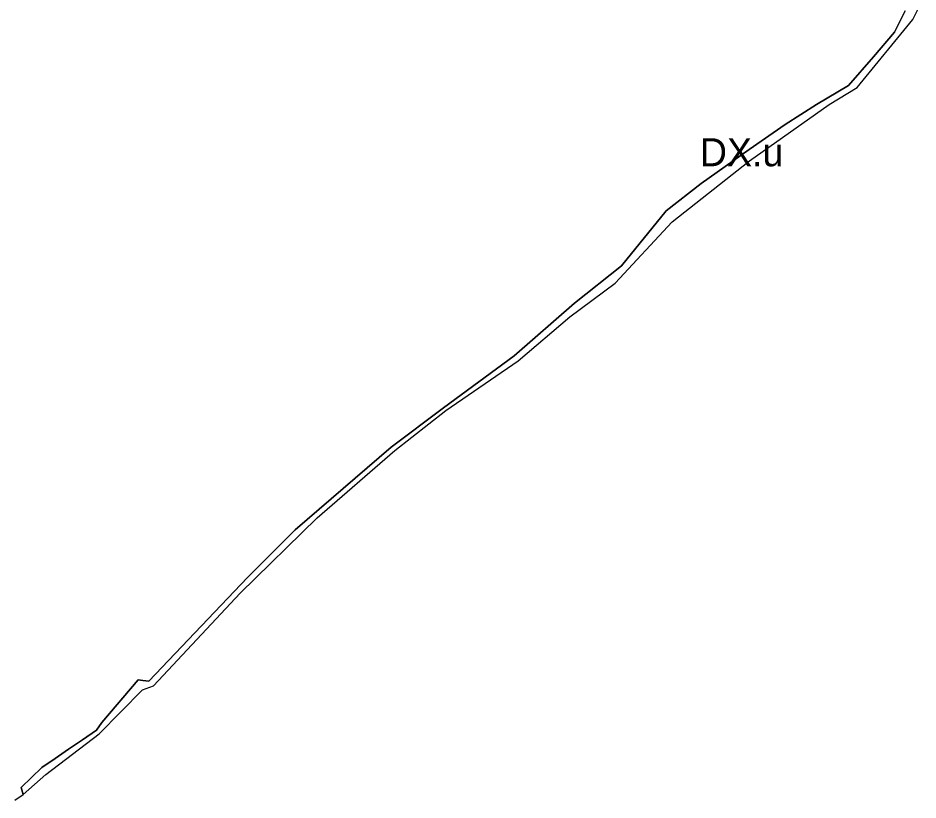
# Model space of a CAD drawing. Extents: x -555509 to -553005, y -1186756 to -1182560.
# Drawn here: x -554001 to -553552.4, y -1186624.2 to -1186234.2 of the extents above; entities that cross this region are included whole.
import ezdxf

# ---------------------------------------------------------------- set-up
doc = ezdxf.new("R2010")
doc.units = 0
for name, color, linetype in [('Level 26', 7, 'Continuous'), ('Level 59', 7, 'Continuous'), ('OBRYS_PLOCH', 7, 'Continuous'), ('stav_AP', 7, 'Continuous')]:
    doc.layers.add(name, color=color, linetype=linetype)

msp = doc.modelspace()

# ---------------------------------------------------------------- linework, layer by layer
at = {"layer": 'Level 26'}
for p, q in [((-553558.79, -1186230.64), (-553564.1, -1186241.28)), ((-553555.07, -1186234.96), (-553552.42, -1186229.64)), ((-553582.79, -1186268.92), (-553555.07, -1186234.96)), ((-553564.1, -1186241.28), (-553574.65, -1186253.6)), ((-553574.65, -1186253.6), (-553587.02, -1186267.86)), ((-553587.02, -1186267.86), (-553603.03, -1186277.36)), ((-553596.76, -1186277.4), (-553582.79, -1186268.92)), ((-553603.03, -1186277.36), (-553618.57, -1186287.3)), ((-553636.33, -1186305.38), (-553596.76, -1186277.4)), ((-553618.57, -1186287.3), (-553636.5, -1186299.75)), ((-553636.5, -1186299.75), (-553660.56, -1186316.81)), ((-553674.91, -1186335.85), (-553636.33, -1186305.38)), ((-553660.56, -1186316.81), (-553678, -1186330.31)), ((-553678, -1186330.31), (-553700.22, -1186357.82)), ((-553703.31, -1186366.52), (-553674.91, -1186335.85)), ((-553700.22, -1186357.82), (-553723.59, -1186376.36)), ((-553725.94, -1186383.17), (-553703.31, -1186366.52)), ((-553723.59, -1186376.36), (-553753.69, -1186402.67)), ((-553751.67, -1186405.15), (-553725.94, -1186383.17)), ((-553753.69, -1186402.67), (-553788.9, -1186428.56)), ((-553787.73, -1186429.86), (-553751.67, -1186405.15)), ((-553788.9, -1186428.56), (-553815, -1186448.15)), ((-553813.2, -1186449.85), (-553787.73, -1186429.86)), ((-553815, -1186448.15), (-553862.84, -1186489.41)), ((-553851.86, -1186483.47), (-553813.2, -1186449.85)), ((-553890.24, -1186521.07), (-553851.86, -1186483.47)), ((-553862.84, -1186489.41), (-553886.65, -1186513.24)), ((-553886.65, -1186513.24), (-553935.74, -1186564.89)), ((-553933.5, -1186567.28), (-553890.24, -1186521.07)), ((-553941.21, -1186564.15), (-553959.17, -1186585.56)), ((-553938.83, -1186564.61), (-553941.21, -1186564.15)), ((-553938.94, -1186569.22), (-553933.5, -1186567.28)), ((-553935.74, -1186564.89), (-553938.83, -1186564.61)), ((-553960.55, -1186591.17), (-553938.94, -1186569.22)), ((-553959.17, -1186585.56), (-553961.95, -1186589.32)), ((-553987.15, -1186611.42), (-553960.55, -1186591.17)), ((-553961.95, -1186589.32), (-553968.89, -1186594.08)), ((-553968.89, -1186594.08), (-553975.83, -1186598.76)), ((-553975.83, -1186598.76), (-553982.5, -1186603.44)), ((-553982.5, -1186603.44), (-553989.2, -1186607.89)), ((-553989.2, -1186607.89), (-553999.39, -1186617.91)), ((-553998.51, -1186621.48), (-553987.15, -1186611.42)), ((-553999.39, -1186617.91), (-553998.51, -1186621.48))]:
    msp.add_line(p, q, dxfattribs=at)
at = {"layer": 'OBRYS_PLOCH'}
for p, q in [((-553558.79, -1186230.64), (-553564.1, -1186241.28)), ((-553564.1, -1186241.28), (-553558.79, -1186230.64)), ((-553555.07, -1186234.96), (-553552.42, -1186229.64)), ((-553582.79, -1186268.92), (-553555.07, -1186234.96)), ((-553564.1, -1186241.28), (-553574.65, -1186253.6)), ((-553574.65, -1186253.6), (-553564.1, -1186241.28)), ((-553574.65, -1186253.6), (-553587.02, -1186267.86)), ((-553587.02, -1186267.86), (-553574.65, -1186253.6)), ((-553587.02, -1186267.86), (-553603.03, -1186277.36)), ((-553603.03, -1186277.36), (-553587.02, -1186267.86)), ((-553596.76, -1186277.4), (-553582.79, -1186268.92)), ((-553603.03, -1186277.36), (-553618.57, -1186287.3)), ((-553618.57, -1186287.3), (-553603.03, -1186277.36)), ((-553636.33, -1186305.38), (-553596.76, -1186277.4)), ((-553618.57, -1186287.3), (-553636.5, -1186299.75)), ((-553636.5, -1186299.75), (-553618.57, -1186287.3)), ((-553636.5, -1186299.75), (-553660.56, -1186316.81)), ((-553660.56, -1186316.81), (-553636.5, -1186299.75)), ((-553674.91, -1186335.85), (-553636.33, -1186305.38)), ((-553660.56, -1186316.81), (-553678, -1186330.31)), ((-553678, -1186330.31), (-553660.56, -1186316.81)), ((-553678, -1186330.31), (-553700.22, -1186357.82)), ((-553700.22, -1186357.82), (-553678, -1186330.31)), ((-553703.31, -1186366.52), (-553674.91, -1186335.85)), ((-553700.22, -1186357.82), (-553723.59, -1186376.36)), ((-553723.59, -1186376.36), (-553700.22, -1186357.82)), ((-553725.94, -1186383.17), (-553703.31, -1186366.52)), ((-553723.59, -1186376.36), (-553753.69, -1186402.67)), ((-553753.69, -1186402.67), (-553723.59, -1186376.36)), ((-553751.67, -1186405.15), (-553725.94, -1186383.17)), ((-553753.69, -1186402.67), (-553788.9, -1186428.56)), ((-553788.9, -1186428.56), (-553753.69, -1186402.67)), ((-553787.73, -1186429.86), (-553751.67, -1186405.15)), ((-553788.9, -1186428.56), (-553815, -1186448.15)), ((-553815, -1186448.15), (-553788.9, -1186428.56)), ((-553813.2, -1186449.85), (-553787.73, -1186429.86)), ((-553815, -1186448.15), (-553862.84, -1186489.41)), ((-553862.84, -1186489.41), (-553815, -1186448.15)), ((-553851.86, -1186483.47), (-553813.2, -1186449.85)), ((-553890.24, -1186521.07), (-553851.86, -1186483.47)), ((-553862.84, -1186489.41), (-553886.65, -1186513.24)), ((-553886.65, -1186513.24), (-553862.84, -1186489.41)), ((-553886.65, -1186513.24), (-553935.74, -1186564.89)), ((-553935.74, -1186564.89), (-553886.65, -1186513.24)), ((-553933.5, -1186567.28), (-553890.24, -1186521.07)), ((-553941.21, -1186564.15), (-553959.17, -1186585.56)), ((-553959.17, -1186585.56), (-553941.21, -1186564.15)), ((-553938.83, -1186564.61), (-553941.21, -1186564.15)), ((-553941.21, -1186564.15), (-553938.83, -1186564.61)), ((-553938.94, -1186569.22), (-553933.5, -1186567.28)), ((-553935.74, -1186564.89), (-553938.83, -1186564.61)), ((-553938.83, -1186564.61), (-553935.74, -1186564.89)), ((-553960.55, -1186591.17), (-553938.94, -1186569.22)), ((-553959.17, -1186585.56), (-553961.95, -1186589.32)), ((-553961.95, -1186589.32), (-553959.17, -1186585.56)), ((-553987.15, -1186611.42), (-553960.55, -1186591.17)), ((-553961.95, -1186589.32), (-553968.89, -1186594.08)), ((-553968.89, -1186594.08), (-553961.95, -1186589.32)), ((-553968.89, -1186594.08), (-553975.83, -1186598.76)), ((-553975.83, -1186598.76), (-553968.89, -1186594.08)), ((-553975.83, -1186598.76), (-553982.5, -1186603.44)), ((-553982.5, -1186603.44), (-553975.83, -1186598.76)), ((-553982.5, -1186603.44), (-553989.2, -1186607.89)), ((-553989.2, -1186607.89), (-553982.5, -1186603.44)), ((-553989.2, -1186607.89), (-553999.39, -1186617.91)), ((-553999.39, -1186617.91), (-553989.2, -1186607.89)), ((-553998.51, -1186621.48), (-553987.15, -1186611.42)), ((-553999.39, -1186617.91), (-553998.51, -1186621.48)), ((-553998.51, -1186621.48), (-553999.39, -1186617.91)), ((-554002.67, -1186624.15), (-553998.51, -1186621.48))]:
    msp.add_line(p, q, dxfattribs=at)
at = {"layer": 'stav_AP'}
for p, q in [((-553564.1, -1186241.28), (-553558.79, -1186230.64)), ((-553574.65, -1186253.6), (-553564.1, -1186241.28)), ((-553587.02, -1186267.86), (-553574.65, -1186253.6)), ((-553603.03, -1186277.36), (-553587.02, -1186267.86)), ((-553618.57, -1186287.3), (-553603.03, -1186277.36)), ((-553636.5, -1186299.75), (-553618.57, -1186287.3)), ((-553660.56, -1186316.81), (-553636.5, -1186299.75)), ((-553678, -1186330.31), (-553660.56, -1186316.81)), ((-553700.22, -1186357.82), (-553678, -1186330.31)), ((-553723.59, -1186376.36), (-553700.22, -1186357.82)), ((-553753.69, -1186402.67), (-553723.59, -1186376.36)), ((-553788.9, -1186428.56), (-553753.69, -1186402.67)), ((-553815, -1186448.15), (-553788.9, -1186428.56)), ((-553862.84, -1186489.41), (-553815, -1186448.15)), ((-553886.65, -1186513.24), (-553862.84, -1186489.41)), ((-553935.74, -1186564.89), (-553886.65, -1186513.24)), ((-553959.17, -1186585.56), (-553941.21, -1186564.15)), ((-553941.21, -1186564.15), (-553938.83, -1186564.61)), ((-553938.83, -1186564.61), (-553935.74, -1186564.89)), ((-553961.95, -1186589.32), (-553959.17, -1186585.56)), ((-553968.89, -1186594.08), (-553961.95, -1186589.32)), ((-553975.83, -1186598.76), (-553968.89, -1186594.08)), ((-553982.5, -1186603.44), (-553975.83, -1186598.76)), ((-553989.2, -1186607.89), (-553982.5, -1186603.44)), ((-553999.39, -1186617.91), (-553989.2, -1186607.89)), ((-553998.51, -1186621.48), (-553999.39, -1186617.91)), ((-554002.67, -1186624.15), (-553998.51, -1186621.48))]:
    msp.add_line(p, q, dxfattribs=at)

# ---------------------------------------------------------------- texts
at = {"layer": 'Level 59'}
msp.add_text('DX.u', height=14, dxfattribs=at).set_placement((-553661.16, -1186308.15))

doc.saveas('drawing.dxf')
